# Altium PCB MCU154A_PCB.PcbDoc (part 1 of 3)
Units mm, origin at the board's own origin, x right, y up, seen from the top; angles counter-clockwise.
Board outline 105 x 85 mm, 2 copper layers (Top Layer, Bottom Layer), stack 1.6 mm thick; 186 components, 100 nets, 433 pads, 196 vias.
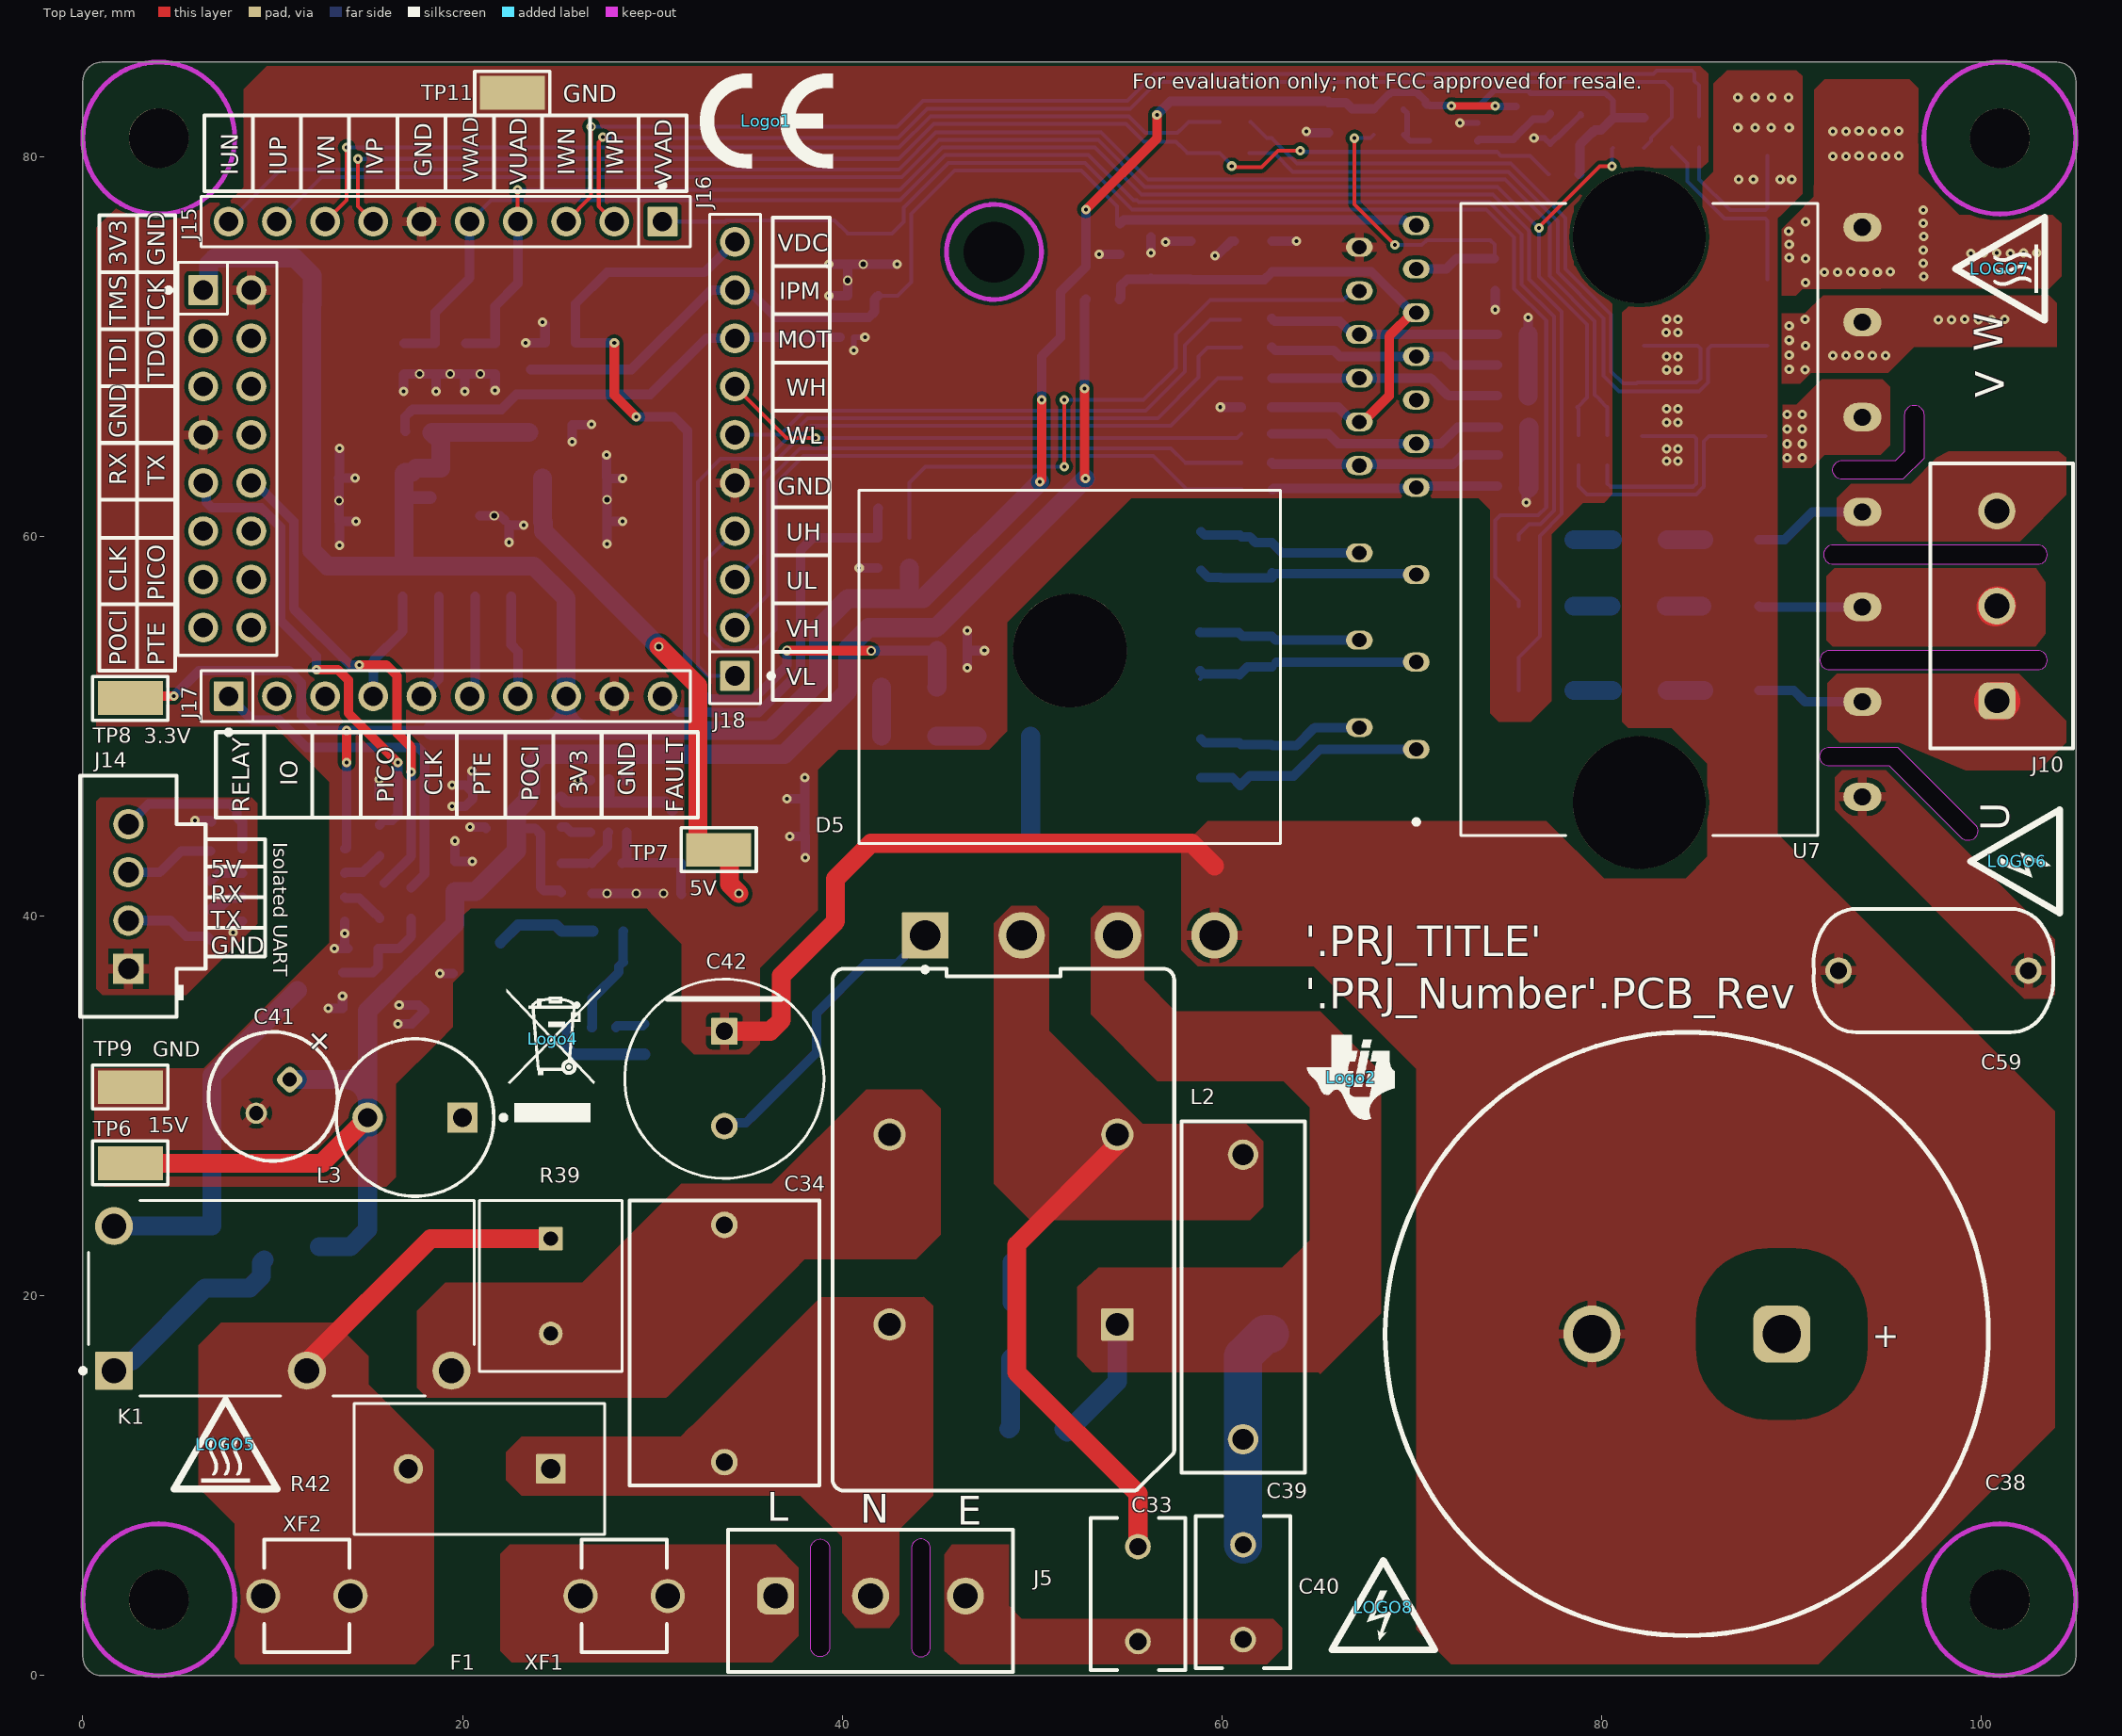
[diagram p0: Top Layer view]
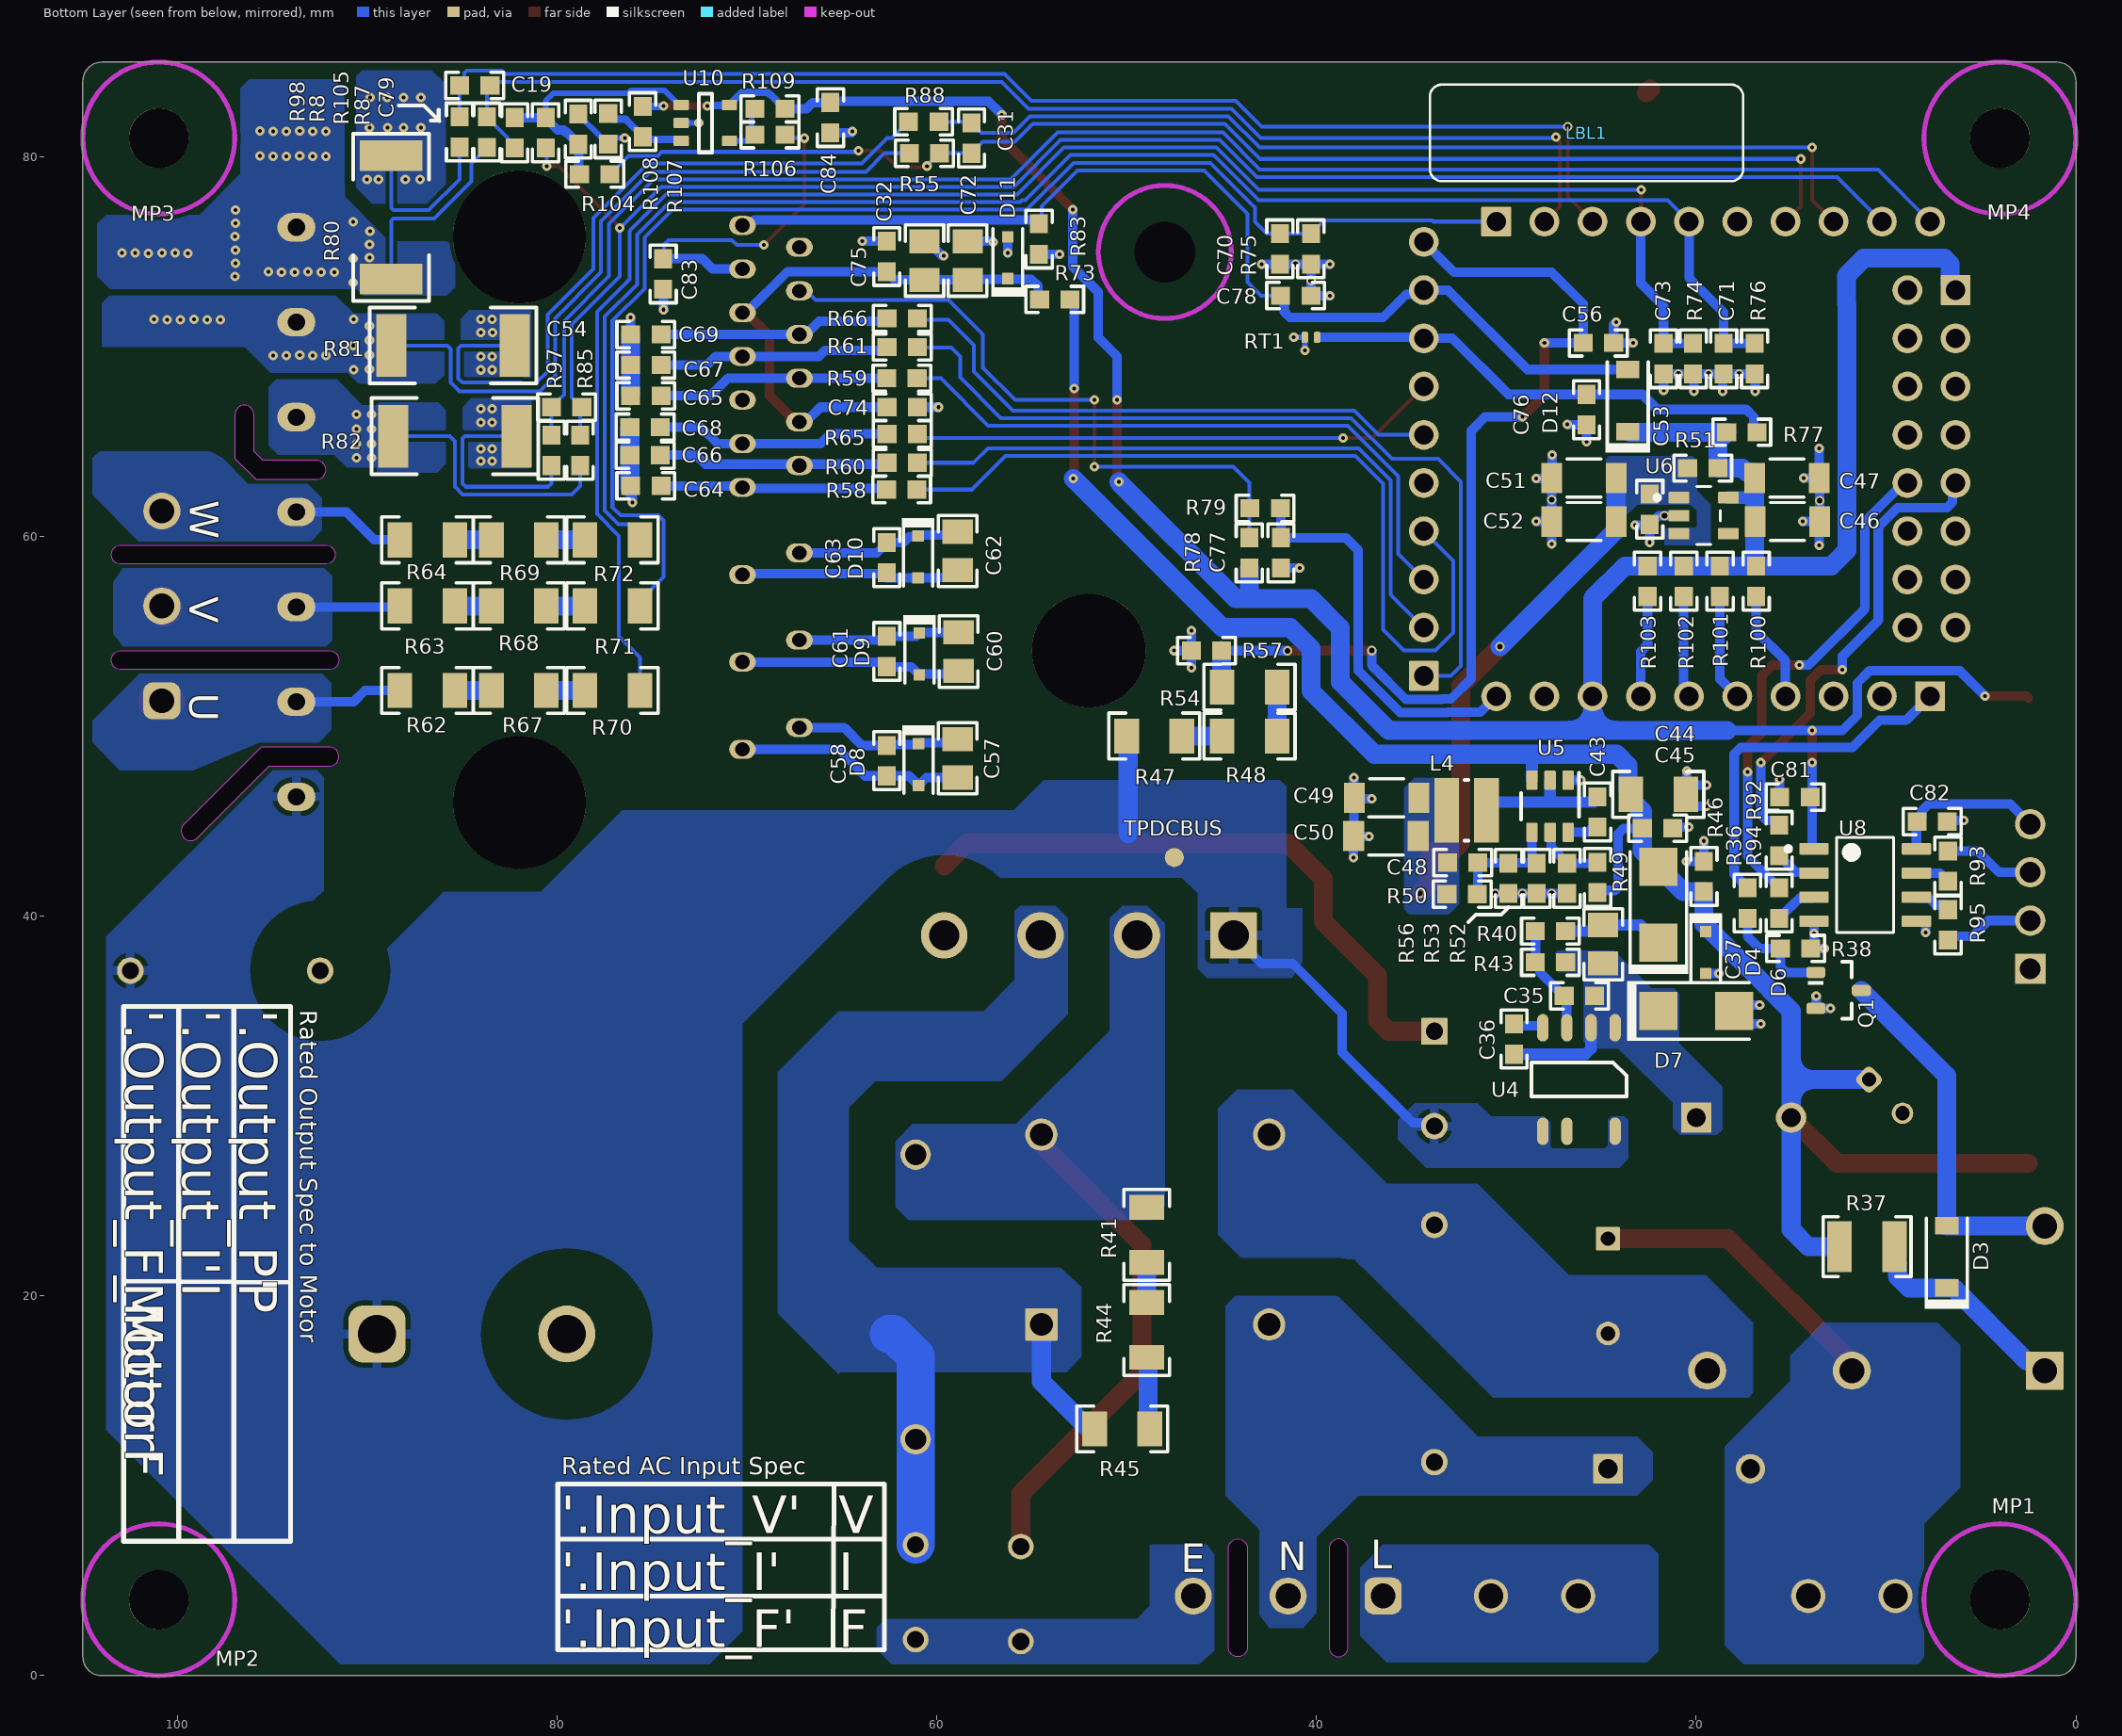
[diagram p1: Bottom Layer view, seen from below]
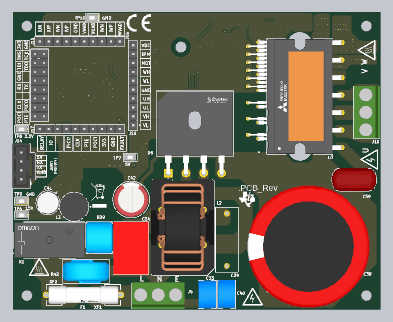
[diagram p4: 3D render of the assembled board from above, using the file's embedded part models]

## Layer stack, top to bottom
Top Solder: solder mask 0.0102, Solder Resist, Dk 3.5
Top Layer: signal copper 0.07
Dielectric1: core 1.46, FR-4 High Tg, Dk 4.8
Bottom Layer: signal copper 0.07
Bottom Solder: solder mask 0.0102, Solder Resist, Dk 3.5

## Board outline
1,0 cw(c1,1) 0,1 0,84 cw(c1,84) 1,85 104,85 cw(c104,84) 105,84 105,1 cw(c104,1) 104,0
cut-out: 92.695,63.017 cw(c92.695,63.517) 92.695,64.017 95.514,64.017 95.988,64.492 95.988,66.431 cw(c96.488,66.431) 96.988,66.431 96.988,64.115 95.89,63.017
cut-out: 92.209,58.554 103,58.554 ccw(c103,59.054) 103,59.554 92.209,59.554 ccw(c92.209,59.054)
cut-out: 92.017,52.995 103,52.995 ccw(c103,53.495) 103,53.995 92.017,53.995 ccw(c92.017,53.495)
cut-out: 92.017,47.918 cw(c92.017,48.418) 92.017,48.918 95.6,48.918 99.673,44.845 cw(c99.319,44.491) 98.966,44.138 95.185,47.918
cut-out: 43.652,1.5 ccw(c44.151,1.5) 44.651,1.5 44.651,6.7 ccw(c44.151,6.7) 43.651,6.7 43.652,6.7
cut-out: 38.348,1.5 38.348,6.7 cw(c38.848,6.7) 39.348,6.7 39.348,1.5 cw(c38.848,1.5)

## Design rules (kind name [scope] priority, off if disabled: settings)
AcuteAngle [All] p1: minimum=4.50000000000000E+0001 checktracksonly=FALSE
AssemblyTestPointUsage [All] p1: valid=2
BoardOutlineClearance BoardOutlineClearance_MountingHoles [OnCopper and InComponentClass('Mounting Holes')] p1: gap=0 ignorepadtopadclearanceinfootprint=FALSE
BoardOutlineClearance BoardOutlineClearance_Poly [OnCopper and IsPoly] p2: gap=0 ignorepadtopadclearanceinfootprint=FALSE
BoardOutlineClearance [OnCopper and Not InComponentClass('Logo') and not InComponentClass('FiducialMark') and not InRegion(1000,500,4000,800) and not InPoly] p3: gap=0 ignorepadtopadclearanceinfootprint=FALSE
Clearance PB+ToPB- [InNetClass('HV') vs InNetClass('LV_Signal')] p1: gap=3 ignorepadtopadclearanceinfootprint=TRUE
Clearance PB-ToACN [InNetClass('LV Signal') vs InNetClass('ACN')] p2: gap=3 ignorepadtopadclearanceinfootprint=TRUE
Clearance ACLToACN [InNetClass('ACL') vs InNetClass('ACN')] p3: gap=2 ignorepadtopadclearanceinfootprint=FALSE
Clearance ISOToAll [InNetClass('Isolation') vs not InNetClass('Isolation')   and (not  OnLayer('Keep-Out Layer'))] p4: gap=6 ignorepadtopadclearanceinfootprint=TRUE
Clearance PB-ToACL [InNetClass('LV Signal') vs InNetClass('ACL')] p5: gap=3 ignorepadtopadclearanceinfootprint=TRUE
Clearance PB+ToACL [InNetClass('V_BUS') vs InNetClass('ACL')] p6: gap=3 ignorepadtopadclearanceinfootprint=TRUE
Clearance PB+ToACN [InNetClass('V_BUS') vs InNetClass('ACN')] p7: gap=1.5 ignorepadtopadclearanceinfootprint=TRUE
Clearance SMTPadToTHHole [not IsVia and OnLayer('Multi-Layer') and not InComponent('J1') and not InComponent('J2') and not InComponent('J3') and not InComponent('J4') and not InComponent('J12') and PadIsPlated vs InSMTComponent and OnLayer('Bottom Layer') and not HasFootprint('TP_SM_1MM')] p8: gap=0.15 ignorepadtopadclearanceinfootprint=FALSE except(3: SMDPad-THPad)
Clearance [All vs not HasFootprint('fiducial10-20')] p9: gap=0.2 ignorepadtopadclearanceinfootprint=TRUE
ComponentClearance ComponentClearance_MountingHoles_FiducialMarks [InComponentClass('Mounting Holes') vs InComponentClass('FiducialMark')] p1: gap=1.27 collisioncheckmode=3 verticalgap=0.254 showdistances=FALSE
ComponentClearance ComponentClearance_Shunt [InComponentClass('Header') vs InComponentClass('Shunt')] p2: gap=0 collisioncheckmode=3 verticalgap=0 showdistances=FALSE
ComponentClearance ComponentClearance_Logo [InComponentClass('Logo')] p3: gap=0.762 collisioncheckmode=3 verticalgap=0.254 showdistances=FALSE
ComponentClearance ComponentClearance_ScrewToNut [(HasFootprint('NY PMS 440 0025 PH')) vs (HasFootprint('Keystone_1902C'))] p4: gap=0.127 collisioncheckmode=3 verticalgap=0.254 showdistances=FALSE
ComponentClearance ComponentClearance_MountingHoles [InComponentClass('Mounting Holes')] p5: gap=2.54 collisioncheckmode=3 verticalgap=2540 showdistances=FALSE
ComponentClearance ComponentClearance_SmallPassives [HasFootprint('0201*') or HasFootprint('0402*') or HasFootprint('0508') or HasFootprint('0603*') or HasFootprint('0612') or HasFootprint('0805*') or HasFootprint('0815*') or HasFootprint('0830*') or HasFootprint('1206*') or HasFootprint('1210*') or HasFootprint('1808*') or HasFootprint('1812*') or HasFootprint('1825*') or HasFootprint('2010*') or HasFootprint('2220*') or HasFootprint('2225*') or HasFootprint('2512*') or HasFootprint('2728*') or HasFootprint('3518*') vs HasFootprint('0201*') or HasFootprint('0402*') or HasFootprint('0508') or HasFootprint('0603*') or HasFootprint('0612') or HasFootprint('0805*') or HasFootprint('0815*') or HasFootprint('0830*') or HasFootprint('1206*') or HasFootprint('1210*') or HasFootprint('1808*') or HasFootprint('1812*') or HasFootprint('1825*') or HasFootprint('2010*') or HasFootprint('2220*') or HasFootprint('2225*') or HasFootprint('2512*') or HasFootprint('2728*') or HasFootprint('3518*')] p6: gap=0.38 collisioncheckmode=3 verticalgap=0.254 showdistances=FALSE
ComponentClearance ComponentClearance_THtoSMT [IsThruComponent vs IsSMTComponent] p7: gap=0.762 collisioncheckmode=3 verticalgap=0.762 showdistances=FALSE
ComponentClearance ComponentClearance_THtoTH [IsThruComponent vs IsThruComponent] p8: gap=0.508 collisioncheckmode=3 verticalgap=0.762 showdistances=FALSE
ComponentClearance [All] p9: gap=0.508 collisioncheckmode=3 verticalgap=0.254 showdistances=FALSE
DiffPairsRouting [All] p1: maxlimit=2.54 minlimit=0.254 mostfreqgap=0.254 toplayer_minwidth=0.381 toplayer_maxwidth=0.381 toplayer_prefwidth=0.381 bottomlayer_minwidth=0.381 bottomlayer_maxwidth=0.381 bottomlayer_prefwidth=0.381 maxuncoupledlength=25.4
FabricationTestPointUsage TestPointUsage [All] p1: valid=2 allowmultiple=FALSE
FabricationTestpoint Testpoint [All] p1: side=3 testpointundercomponent=TRUE minsize=1.016 maxsize=2.54 preferedsize=1.524 minholesize=0 maxholesize=1.016 preferedholesize=0.813 testpointgrid=0.025 allowsidetop=TRUE allowsidebottom=TRUE usegrid=TRUE gridtolerance=0
FanoutControl Fanout_LCC [IsLCC] p1: bgadir=Out bgaviamode=Centered fanoutstyle=Auto fanoutdirection=Alternating viagrid=0.025 // Fanout_LCC (Default Rule)
FanoutControl Fanout_BGA [IsBGA] p2: bgadir=Out bgaviamode=Centered fanoutstyle=Auto fanoutdirection=Alternating viagrid=0.025 // Fanout_BGA (Default Rule)
FanoutControl Fanout_Default [All] p4: bgadir=Out bgaviamode=Centered fanoutstyle=Auto fanoutdirection=Alternating viagrid=0.025 // Fanout_Default (Default Rule)
FanoutControl Fanout_Small [(CompPinCount < 5)] p5: bgadir=Out bgaviamode=Centered fanoutstyle=Auto fanoutdirection=OutThenIn viagrid=0.025 // Fanout_Small (Default Rule)
HoleSize [All] p1: absolutevalues=TRUE maxlimit=6.375 minlimit=0.2 maxpercent=80.000 minpercent=20.000
MinimumAnnularRing MinimumAnnularRing_ThermalPadVias [IsVia and InAnyComponent] p1: minimumring=0.15
MinimumAnnularRing [All] p2: minimumring=0.2
MinimumSolderMaskSliver MinimumSolderMaskSliver_Logo [InComponentClass('Logo') vs InComponentClass('Logo')] p1: minsoldermaskwidth=0.018
MinimumSolderMaskSliver [All] p2: minsoldermaskwidth=0.1
PlaneConnect [All] p1: planeconnectstyle=Direct reliefexpansion=0.254 reliefentries=4 reliefconductorwidth=0.254 reliefairgap=0.254
PolygonConnect "Thermal relief" [All vs InNet('GND') or innet('GND_ISO')  or innet('ubus')] p1: thpad.connectstyle=Relief thpad.reliefconductorwidth=0.5 thpad.reliefentries=4 thpad.polygonreliefangle="90 Angle" thpad.airgapwidth=0.254 smdpad.connectstyle=Direct smdpad.reliefconductorwidth=0.5 smdpad.reliefentries=4 smdpad.polygonreliefangle="90 Angle" smdpad.airgapwidth=0.254 via.connectstyle=Direct via.reliefconductorwidth=0.5 via.reliefentries=4 via.polygonreliefangle="90 Angle" via.airgapwidth=0.254
PolygonConnect [All] p2: connectstyle=Direct reliefconductorwidth=0.254 reliefentries=4 polygonreliefangle="90 Angle" airgapwidth=0.254
RoutingVias ThermalPadVias [IsVia and InAnyComponent] p1: holewidth=0.2 width=0.5 viastyle="Through Hole" minholewidth=0.2 minwidth=0.5 maxholewidth=0.33 maxwidth=0.6
RoutingVias [All] p2: holewidth=0.2 width=0.5 viastyle="Through Hole" minholewidth=0.2 minwidth=0.4 maxholewidth=1 maxwidth=1.4
SilkToBoardRegionClearance [Not ((IsComment or IsDesignator) And (Hide <> 'False')) and not InRegion(1000,500,4000,800)] p1:
SilkToSilkClearance SilkToSilkClearance_Pb-FreeLogo [(HasFootprint('Pb-Free_Overlay_Medium') OR HasFootprint('Pb-Free_Overlay_Small')) vs (HasFootprint('Pb-Free_Overlay_Medium') OR HasFootprint('Pb-Free_Overlay_Small'))] p1: silktosilkclearance=0
SilkToSilkClearance [All] p2: silktosilkclearance=0.1
SilkToSolderMaskClearance SilkToComponentPadClearance [(IsPad or IsFill or IsRegion) and InAnycomponent] p1: minsilkscreentomaskgap=0.127 clearancetoexposedcopper=TRUE
SilkToSolderMaskClearance "Silk to Solder Mask Opening" [All] p2: minsilkscreentomaskgap=0.1 clearancetoexposedcopper=FALSE
SolderMaskExpansion [All] p1: expansion=0.05 istentingtop=FALSE
UnRoutedNet [All] p1: checkbadconnections=TRUE
Width [All] p1: maxlimit=5 minlimit=0.2 preferedwidth=0.3 minimp=50.000000 maximp=50.000000 favimp=50.000000 checkconnectedcopper=TRUE
14 further rules are at their usual default settings.

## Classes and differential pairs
component class MCU154A_Main: J5 J10
net class LV_Signal: 3.3V 5V 5V_ISO 15V GND GND_ISO IPM_15V IPM_CIN IPM_FAULT IPM_PWM_UH IPM_PWM_UL IPM_PWM_VH IPM_PWM_VL IPM_PWM_WH IPM_PWM_WL IPM_TEMP_AD IU_N IU_P IV_N IV_P IW_N IW_P MCU_TCK MCU_TDI MCU_TDO MCU_TMS MISC_IO MOTOR_TEMP_AD NetC43_1 NetC43_2 NetC48_2 NetC79_1 NetD3_1 NetD3_2 NetQ1_1 NetR8_1 NetR49_1 NetR55_1 NetR78_2 NetR82_2 NetR92_2 NetR93_1 NetR94_2 NetR95_1 NetR106_1 NetR107_1 NetU4_6 NetU6_4 NetU7_12 PWM_UH PWM_UL PWM_VH PWM_VL PWM_WH PWM_WL RELAY SPI_CLK(AI) SPI_CLK(DAC) SPI_PICO(AI) SPI_PICO(DAC) SPI_POCI(AI) SPI_POCI(DAC) SPI_PTE(AI) SPI_PTE(DAC) UART_RX UART_RX_ISO UART_TX UART_TX_ISO VDC_AD VU_AD VV_AD VW_AD
net class HV: Ubus
net class ACN: NetC39_2 NetR44_1 NEU
net class ACL: NetC33_1 NetC34_1 NetK1_2
component class Designator: C81 C82 J15 J16 J17 J18 R92 R93 R94 R95 R100 R101 R102 R103 U8
component class Logo: Logo2
component class Label: LBL1
component class Designator: C19 C31 C32 C54 C57 C58 C59 C60 C61 C62 C63 C64 C65 C66 C67 C68 C69 C70 C71 C72 C73 C74 C75 C76 C77 C78 C79 C83 C84 D8 D9 D10 D11 D12 R8 R55 R58 R59 R60 R61 R62 R63 R64 R65 R66 R67 R68 R69 R70 R71 R72 R73 R74 R75 R76 R77 R78 R79 R80 R81 R82 R83 R85 R87 R88 R97 R98 R104 R105 R106 R107 R108 R109 RT1 U7 U10

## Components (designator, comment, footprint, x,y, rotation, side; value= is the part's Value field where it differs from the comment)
C19 "GRM188R71E102KA01D" 0603 84.352,83.773 r180 bottom value=1000pF
C31 "GRM188R71E102KA01D" 0603 58.183,81 r270 bottom value=1000pF
C32 "GRM21BR6YA106KE43L" 0805_HV 60.662,74.548 r90 bottom value=10uF
C33 "DE2E3KY222MA2BM01F" KY_800x500x1100 55.588,4.3 r270 top value=2200pF
C34 "890324024005" WCAP-FTX2_1500x1000x1600 33.8,17.5 r270 top value=0.47uF
C35 "GRM1885C1H200JA01D" 0603 26.156,35.81 r180 bottom value=20pF
C36 "GCM188R71H104KA57D" 0603 29.6,33.537 r270 bottom value=0.1uF
C37 "GRM219R71H334KA88D" 0805_HV 24.907,38.531 r270 bottom value=0.33uF
C38 "861141486026" WCAP-AI3H_3500x5700 84.5,18 r180 top value=680uF
C39 "890324025017" WCAP-FTX2_1800x600x1200 61.126,19.95 r270 top value=0.1uF
C40 "DE2E3KY222MA2BM01F" KY_800x500x1100 61.126,4.4 r90 top value=2200pF
C41 "35ZLJ100M6.3X11" Rubycon_630x1100 10.016,30.516 r225 top value=100uF
C42 "860241375002" FP-860241375002_RADIAL-MFG 33.8,31.45 r270 top locked value=10µF
C43 "GCM188R71H104KA57D" 0603 25.2,45.5 r90 bottom value=0.1uF
C44 "GRM319R6YA106KA12D" 1206 22,46.426 r180 bottom value=10uF
C45 "GCM188R71H104KA57D" 0603 22.038,44.641 r180 bottom value=0.1uF
C46 "GRM31CR71E106KA12L" 1206_180 15.2,60.8 r180 bottom value=10uF
C47 "GRM31CR71E106KA12L" 1206_180 15.224,63.089 r180 bottom value=10uF
C48 "GRM1885C1H101JA01D" 0603 32.307,42.831 r180 bottom value=100pF
C49 "GRM31CR71E106KA12L" 1206_180 36.349,44.23 r0 bottom value=10uF
C50 "GRM31CR71E106KA12L" 1206_180 36.309,46.25 r0 bottom value=10uF
C51 "GRM31CR71E106KA12L" 1206_180 25.921,63.089 r0 bottom value=10uF
C52 "GRM31CR71E106KA12L" 1206_180 25.921,60.8 r0 bottom value=10uF
C53 "GCM188R71H104KA57D" 0603 22.452,61.445 r270 bottom value=0.1uF
C54 "GRM188R71E102KA01D" 0603 79.515,66.825 r180 bottom value=1000pF
C56 "GRM188R71H473KA61D" 0603 25.152,70.209 r180 bottom value=0.047uF
C57 "GRM21BR6YA106KE43L" 0805_HV 58.913,48.326 r90 bottom value=10uF
C58 "GCM188R71H104KA57D" 0603 62.644,48.2 r90 bottom value=0.1uF
C59 "ECW-FD2W474Q1" ECWFD_1260x650x1270 97.5,37.142 r180 top value=0.47uF
C60 "GRM21BR6YA106KE43L" 0805_HV 58.864,53.952 r90 bottom value=10uF
C61 "GCM188R71H104KA57D" 0603 62.644,53.952 r90 bottom value=0.1uF
C62 "GRM21BR6YA106KE43L" 0805_HV 58.913,59.249 r90 bottom value=10uF
C63 "GCM188R71H104KA57D" 0603 62.646,58.9 r90 bottom value=0.1uF
C64 "GRM188R71H221KA01D" 0603 75.34,62.679 r180 bottom value=220pF
C65 "GRM188R71H221KA01D" 0603 75.34,67.424 r180 bottom value=220pF
C66 "GRM188R71H221KA01D" 0603 75.378,64.297 r180 bottom value=220pF
C67 "GRM188R71H221KA01D" 0603 75.34,69.04 r180 bottom value=220pF
C68 "GRM188R71H221KA01D" 0603 75.378,65.772 r180 bottom value=220pF
C69 "GRM188R71H221KA01D" 0603 75.34,70.65 r180 bottom value=220pF
C70 "GRM188R71H473KA61D" 0603 41.933,75.163 r270 bottom value=0.047uF
C71 "GRM188R71H473KA61D" 0603 18.559,69.378 r270 bottom value=0.047uF
C72 "GRM21BR6YA106KE43L" 0805_HV 58.386,74.548 r90 bottom value=10uF
C73 "GRM188R71H473KA61D" 0603 21.721,69.378 r270 bottom value=0.047uF
C74 "GCM188R71H104KA57D" 0603 61.835,66.825 r180 bottom value=0.1uF
C75 "GCM188R71H104KA57D" 0603 62.646,74.764 r90 bottom value=0.1uF
C76 "GCM188R71H104KA57D" 0603 25.781,66.695 r270 bottom value=0.1uF
C77 "GRM188R71E102KA01D" 0603 41.883,59.15 r270 bottom value=1000pF
C78 "GRM188R71E102KA01D" 0603 41.1,72.7 r0 bottom value=1000pF
C79 "GRM1885C1H101JA01D" 0603 78.897,81.466 r90 bottom value=100pF
C81 "GRJ188R71E105KE11D" 0603 14.8,46.285 r180 bottom value=1uF
C82 "GRJ188R71E105KE11D" 0603 7.567,44.994 r180 bottom value=1uF
C83 "GRM188R71E102KA01D" 0603 74.43,73.844 r270 bottom value=1000pF
C84 "GCM188R71H104KA57D" 0603 65.619,82.08 r270 bottom value=0.1uF
D3 "BAT54T1G" SOD-123 6.8,22.063 r90 bottom value=30V
D4 "US1M-13-F" SMA 22,40.614 r90 bottom value=1000V
D5 "GBU15J" FP-GBU8J_Horizontal_Face_Down_SIP4-MFG 52,53.15 r0 top locked
D6 "MMSZ5248BS-7-F" SOD-323 19.5,38.1 r270 bottom value=18V
D7 "US1M-13-F" SMA 20,35.016 r180 bottom value=1000V
D8 "MMSZ5248BS-7-F" SOD-323 60.974,48 r270 bottom value=18V
D9 "MMSZ5248BS-7-F" SOD-323 60.926,53.823 r270 bottom value=18V
D10 "MMSZ5248BS-7-F" SOD-323 60.999,58.935 r270 bottom value=18V
D11 "MMSZ5248BS-7-F" SOD-323 56.274,74.699 r90 bottom value=18V
D12 "BAT54T1G" SOD-123 23.61,67.171 r90 bottom value=30V
F1 "0215008.HXP" FP-0215008.HXP_FUSE_CARTRIDGE-MFG 20.146,4.2 r0 top
J5 "691137710003" 691137710003 41.5,3.95 r0 top
J10 "691137710003" 691137710003 101.09,56.351 r90 top
J14 "70543-0038" Molex_70543-0038 2.4,41.05 r90 top
J15 "TSW-108-07-T-D" FP-TSW-108-07-T-D_HDR16-MFG 7.61,64.1 r270 top
J16 "TSW-110-07-T-S" FP-TSW-110-07-T-S_HDR10-MFG 19.11,76.6 r180 top
J17 "TSW-110-07-T-S" FP-TSW-110-07-T-S_HDR10-MFG 19.11,51.6 r0 top
J18 "TSW-110-07-T-S" FP-TSW-110-07-T-S_HDR10-MFG 34.36,64.1 r90 top
K1 "G5Q-1A4-EU DC12" "FP-G5Q-1A4-EU DC12_PTH_RELAY_20MM0_10MM0-MFG" 10.46,19.875 r0 top
L2 "7448040707" WE-CMBNC_L 48.5,23.5 r180 top locked value=7mH
L3 "768772182" WE-TI_8095 17.5,29.4 r180 top value=1.8mH
L4 "78438335068" WE-MAIA_3015 32.1,45.595 r0 bottom value=6.8uH
LBL1 "THT-14-423-10" Label_650x200 25.781,81.276 r180 bottom
Logo1 "CE Mark" CE_Mark_5mm 36,81.9 r0 top
Logo2 "Texas Instruments" TI_Symbol_Overlay_Small 66.8,31.518 r0 top
Logo3 "FCC disclaimer" FCC_disclaimer 47.377,95 r0 top
Logo4 "WEEE logo" WEEE_Minimum 24.74,33.543 r0 top
LOGO5 "CAUTION HOT SURFACE" IEC_HotSurface_Small 7.518,12.2 r0 top
LOGO6 "DANGER HIGH VOLTAGE" IEC_HighVoltage_Small 101.91,42.9 r90 top
LOGO7 "CAUTION HOT SURFACE" IEC_HotSurface_Small 101,74.115 r90 top
LOGO8 "DANGER HIGH VOLTAGE" IEC_HighVoltage_Small 68.511,3.6 r0 top
M46 "Comment" MARK 559.6,31.8 r0 top
M47 "Comment" Toolinghole 544.6,30.3 r0 top
M49 "Comment" MARK 554.6,31.8 r0 top
M50 "Comment" MARK 399.6,31.8 r0 top
M51 "Comment" MARK 399.602,138.799 r0 top
M52 "Comment" MARK 559.6,138.8 r0 top
M53 "Comment" Toolinghole 409.6,30.3 r0 top
M54 "Comment" Toolinghole 409.602,140.299 r0 top
M55 "Comment" Toolinghole 549.6,140.3 r0 top
M56 "Comment" Arrow 424.6,140.3 r0 top
M57 "Comment" Arrow 467.6,140.3 r180 bottom
M57 "Comment" "Bad Mark" 484.6,31.8 r0 top
M58 "Comment" "Bad Mark" 474.6,31.8 r0 top
M58 "Comment" "White oil-26X4" 524.6,28.3 r0 top
MP1 "970130365" FP-970130365_SPCAER_M3-MFG 4,4 r180 bottom locked
MP2 "970130365" FP-970130365_SPCAER_M3-MFG 101,4 r180 bottom locked
MP3 "970130365" FP-970130365_SPCAER_M3-MFG 101,81 r180 bottom
MP4 "970130365" FP-970130365_SPCAER_M3-MFG 4,81 r180 bottom
Q1 "2N7002P,215" SOT-23 12.5,36.1 r180 bottom value=60V
R8 "RC0603FR-0720RL" 0603 83.715,81.315 r90 bottom value=20.0
R36 "RC0603FR-071KL" 0603 17.3,40.7 r270 bottom value=1.00k
R37 "RC1210FR-07180RL" 1210 11,22.6 r180 bottom value=180
R38 "RC0603FR-0710KL" 0603 14.768,38.309 r0 bottom value=10.0k
R39 "B59770C0120A070" FP-B59770C0120A070_RADIAL-MFG 24.65,20.525 r270 top value=70¦¸
R40 "RC0603FR-07133KL" 0603 27.68,39.222 r180 bottom value=133k
R41 "RC1206FR-07100KL" 1206 48.952,23.223 r90 bottom value=100k
R42 "IsoM3-275-B-L2" FP-IsoM3-275-B-L2_RADIAL-MFG 20.9,10.9 r180 top
R43 "RC0603FR-0710KL" 0603 27.68,37.583 r0 bottom value=10.0k
R44 "RC1206FR-07100KL" 1206 48.952,18.213 r90 bottom value=100k
R45 "RC1206FR-07100KL" 1206 50.239,13 r180 bottom value=100k
R46 "RC0603FR-0720KL" 0603 19.6,42.1 r270 bottom value=20.0k
R47 "RC1206FR-07332KL" 1206 48.555,49.5 r0 bottom value=332k
R48 "RC1206FR-07332KL" 1206 43.535,49.5 r0 bottom value=332k
R49 "RC0603FR-071M5L" 0603 25.2,42.052 r270 bottom value=1.50Meg
R50 "RC0603FR-07100KL" 0603 32.337,41.169 r0 bottom value=100k
R51 "RC0603JR-070RL" 0603 19.659,63.612 r180 bottom value=0
R52 "RC0603FR-07133KL" 0603 26.811,42 r90 bottom value=133k
R53 "RC0603FR-0713K7L" 0603 28.401,42 r90 bottom value=13.7k
R54 "RC1206FR-07332KL" 1206 43.535,52.073 r180 bottom value=332k
R55 "RC0603FR-0720RL" 0603 60.662,80.2 r180 bottom value=20.0
R56 "RC0603FR-0720KL" 0603 29.891,42 r90 bottom value=20.0k
R57 "RC0603FR-078K2L" 0603 45.8,54 r180 bottom value=8.20k
R58 "RC0603FR-07100RL" 0603 61.862,62.484 r0 bottom value=100
R59 "RC0603FR-07100RL" 0603 61.844,68.349 r0 bottom value=100
R60 "RC0603FR-07100RL" 0603 61.835,63.898 r0 bottom value=100
R61 "RC0603FR-07100RL" 0603 61.835,69.992 r0 bottom value=100
R62 "RC1206FR-07332KL" 1206 86.847,51.9 r0 bottom value=332k
R63 "RC1206FR-07332KL" 1206 86.847,56.351 r0 bottom value=332k
R64 "RC1206FR-07332KL" 1206 86.847,59.835 r0 bottom value=332k
R65 "RC0603FR-07100RL" 0603 61.835,65.414 r0 bottom value=100
R66 "RC0603FR-07100RL" 0603 61.835,71.502 r0 bottom value=100
R67 "RC1206FR-07332KL" 1206 82.029,51.9 r0 bottom value=332k
R68 "RC1206FR-07332KL" 1206 82.029,56.351 r0 bottom value=332k
R69 "RC1206FR-07332KL" 1206 82.029,59.835 r0 bottom value=332k
R70 "RC1206FR-07332KL" 1206 77.1,51.9 r0 bottom value=332k
R71 "RC1206FR-07332KL" 1206 77.1,56.351 r0 bottom value=332k
R72 "RC1206FR-07332KL" 1206 77.1,59.835 r0 bottom value=332k
R73 "RC0603JR-070RL" 0603 53.8,72.5 r0 bottom value=0
R74 "RC0603FR-078K2L" 0603 20.166,69.378 r90 bottom value=8.20k
R75 "RC0603FR-078K2L" 0603 40.3,75.163 r90 bottom value=8.20k
R76 "RC0603FR-078K2L" 0603 16.923,69.378 r90 bottom value=8.20k
R77 "RC0603FR-071KL" 0603 17.6,65.5 r0 bottom value=1.00k
R78 "RC0603FR-0710KL" 0603 43.545,59.15 r90 bottom value=10.0k
R79 "RC0603FR-07100RL" 0603 42.714,61.496 r0 bottom value=100
R80 "CSRN2512FT50L0" CSRN2512 88.754,76.823 r270 bottom value=0.05
R81 "CSRN2512FT50L0" CSRN2512 85.5,70.068 r0 bottom value=0.05
R82 "CSRN2512FT50L0" CSRN2512 85.397,65.297 r0 bottom value=0.05
R83 "RC0603FR-075K1L" 0603 54.625,75.682 r90 bottom value=5.10k
R85 "RC0603FR-0720RL" 0603 78.807,64.55 r90 bottom value=20.0
R87 "RC0603FR-075K1L" 0603 80.618,81.28 r90 bottom value=5.10k
R88 "RC0603FR-0720RL" 0603 60.702,81.859 r180 bottom value=20.0
R92 "RC0603FR-07100RL" 0603 15.633,44 r270 bottom value=100
R93 "RC0603FR-071KL" 0603 6.734,42.65 r90 bottom value=1.00k
R94 "RC0603FR-071KL" 0603 15.633,40.7 r270 bottom value=1.00k
R95 "RC0603FR-07100RL" 0603 6.738,39.55 r270 bottom value=100
R97 "RC0603FR-0720RL" 0603 80.315,64.55 r90 bottom value=20.0
R98 "RC0603FR-0720RL" 0603 85.152,81.318 r90 bottom value=20.0
R100 "RC0603FR-0710KL" 0603 16.844,57.654 r270 bottom value=10.0k
R101 "RC0603FR-0710KL" 0603 18.751,57.654 r270 bottom value=10.0k
R102 "RC0603FR-0710KL" 0603 20.659,57.654 r270 bottom value=10.0k
R103 "RC0603FR-0710KL" 0603 22.566,57.654 r270 bottom value=10.0k
R104 "RC0603FR-075K1L" 0603 78.033,79.098 r0 bottom value=5.10k
R105 "RC0603FR-075K1L" 0603 82.25,81.28 r90 bottom value=5.10k
R106 "RC0603FR-07100RL" 0603 68.8,81.173 r180 bottom value=100
R107 "RC0603FR-0720KL" 0603 75.505,81.864 r90 bottom value=20.0k
R108 "RC0603FR-071KL" 0603 77.32,81.487 r90 bottom value=1.00k
R109 "RC0603FR-0720KL" 0603 68.8,82.542 r0 bottom value=20.0k
RT1 "TMP6131DECR" DEC0002A 40.3,70.5 r180 bottom
TP6 "5015" Testpoint_Keystone_Miniature 2.5,27 r180 top
TP7 "5015" Testpoint_Keystone_Miniature 33.5,43.5 r180 top
TP8 "5015" Testpoint_Keystone_Miniature 2.5,51.5 r0 top
TP9 "5015" Testpoint_Keystone_Miniature 2.5,31 r180 top
TP11 "5015" Testpoint_Keystone_Miniature 22.626,83.382 r0 top
TPDCBUS "TP_SM_1MM" TP_SM_1MM 47.5,43.1 r0 bottom
U4 "UCC28881DR" D0007A_N 26.18,31.406 r270 bottom
U5 "TPS54202DDCR" DDC0006A_N 27.7,45.8 r270 bottom
U6 "TLV74033PDBVR" DBV0005A-MFG 19.609,61.11 r180 bottom
U7 "SLIMDIP-M" FP-SLIMDIP-S_SLIMDIP-MFG 82,60.9 r90 top locked
U8 "ISO6721BQDRQ1" D0008A-MFG 11.1,41.65 r180 bottom
U10 "LMV331QDBVRQ1" DBV0005A_L 72.204,81.798 r180 bottom
XF1 "01000056Z" Littelfuse_0100-0020_54_56 28.515,4.2 r0 top value=10A
XF2 "01000056Z" Littelfuse_0100-0020_54_56 11.8,4.2 r0 top value=10A

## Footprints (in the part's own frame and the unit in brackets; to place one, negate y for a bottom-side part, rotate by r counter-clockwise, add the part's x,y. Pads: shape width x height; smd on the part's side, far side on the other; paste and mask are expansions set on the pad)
0603 [mm] "0603 from SM-752 data"
  rect 1x0.95 smd: 1(-0.8,0) 2(0.8,0)
  silkscreen extent -1.52,-0.69 1.52,0.69, body extent -0.87,-0.47 0.87,0.47, height 1
0805_HV [mil] "0805 with 30mil clearance between pads"
  rect 50x63 smd: 1(-40,0) 2(40,0)
  silkscreen extent -74,-40 74,40, body extent -43,-29 43,29, height 57
1206 [mm] "1206 from SM-752 data"
  rect 1.3x1.85 smd: 1(-1.45,0) 2(1.45,0)
  silkscreen extent -2.4,-1.21 2.4,1.21, body extent -1.7,-0.9 1.7,0.9, height 1.35
1206_180 [mm] "1206_180"
  rect 1.1x1.6 smd: 1(-1.7,0) 2(1.7,0)
  silkscreen extent -0.9,-1 0.9,1, body extent -1.75,-0.95 1.75,0.95, height 1.8
1210 [mm] "1210 from SM-752 data"
  rect 1.3x2.7 smd: 1(-1.45,0) 2(1.45,0)
  silkscreen extent -2.32,-1.57 2.32,1.57, body extent -1.7,-1.35 1.7,1.35, height 1.35
691137710003 [mm] "Horizontal Cable Entry with Pressure Clamp, pitch 5mm, 03p"
  rrect50% 1.95x1.95 hole 1.3: 1(-5,0.25)
  round 1.95 hole 1.3: 2(0,0.25) 3(5,0.25)
  silkscreen extent -7.5,-3.75 7.5,3.75, body extent -7.5,-3.75 7.5,3.75, height 11.6
Arrow [mm] "·½Ïò¼ýÍ·"
  silkscreen extent 0,-2 43,2
"Bad Mark" [mm]
  round 2 on Bottom Solder: 2(0,0)
  round 2 on Top Solder: 2(0,0)
  Top Layer pour cut-out: -1.051,0 -0.971,-0.402 -0.743,-0.743 -0.402,-0.971 0,-1.051 0,-1.051 0.402,-0.971 0.743,-0.743 0.971,-0.402 1.051,0 1.051,0 0.971,0.402 0.743,0.743 0.402,0.971 0,1.051 0,1.051 -0.402,0.971 -0.743,0.743 -0.971,0.402 -1.051,0
  Top Layer region: -0.5,-0.25 -0.5,0.25 0.5,0.25 0.5,-0.25
  Top Layer region: -0.25,0.5 0.25,0.5 0.25,-0.5 -0.25,-0.5
  Bottom Layer pour cut-out: 1.051,0 0.971,-0.402 0.743,-0.743 0.402,-0.971 0,-1.051 0,-1.051 -0.402,-0.971 -0.743,-0.743 -0.971,-0.402 -1.051,0 -1.051,0 -0.971,0.402 -0.743,0.743 -0.402,0.971 0,1.051 0,1.051 0.402,0.971 0.743,0.743 0.971,0.402 1.051,0
  Bottom Layer region: 0.25,0.5 -0.25,0.5 -0.25,-0.5 0.25,-0.5
  Bottom Layer region: 0.5,-0.25 0.5,0.25 -0.5,0.25 -0.5,-0.25
CE_Mark_5mm [mm] "Minimum text height for CE Mark"
  silkscreen extent -3.5,-2.5 3.5,2.5
CSRN2512 [mm] "STACKPOLE"
  rect 1.6x3.3 smd: 1(-3.25,0) 2(3.25,0)
  silkscreen extent -4.4,-2 4.4,2, body extent -3.27,-1.65 3.27,1.65, height 0.7
D0007A_N [mm] "SOIC, 7-Leads, Body 4.9x3.9mm, Pitch 1.27mm, IPC Medium Density"
  oval 1.45x0.6 smd: 1(-2.725,1.905) 2(-2.725,0.635) 3(-2.725,-0.635) 4(-2.725,-1.905) 5(2.725,-1.905) 6(2.725,-0.635) 8(2.725,1.905)
  silkscreen extent -0.9,-2.5 0.9,2.5, body extent -3.01,-2.45 3.01,2.45, height 1.75
D0008A-MFG [mm]
  rrect17% 1.55x0.6 smd paste+0: 1(-2.7,1.905) 2(-2.7,0.635) 3(-2.7,-0.635) 4(-2.7,-1.905) 5(2.7,-1.905) 6(2.7,-0.635) 7(2.7,0.635) 8(2.7,1.905)
  silkscreen extent -4.17,-2.5 1.5,2.5, body extent -3,-2.45 3,2.45, height 1.75
DBV0005A-MFG [mm]
  rrect17% 1.1x0.6 smd paste+0 mask+0: 1(-1.3,0.95) 2(-1.3,0) 3(-1.3,-0.95) 4(1.3,-0.95) 5(1.3,0.95)
  silkscreen extent -2.58,-1.53 0.87,1.53, body extent -1.4,-1.45 1.4,1.45, height 1.45
DBV0005A_L [mm] "SOT23, 5-Leads, Body 2.9x1.6mm, Pitch 0.95mm, Lead Span 2.8mm, IPC High Density"
  rrect18% 0.8x0.55 smd: 1(-1.275,0.95) 2(-1.275,0) 3(-1.275,-0.95) 4(1.275,-0.95) 5(1.275,0.95)
  silkscreen extent -0.35,-1.55 0.35,1.55, body extent -1.42,-1.46 1.42,1.46, height 1.09
DDC0006A_N [mm]
  rrect17% 1x0.6 smd: 1(-1.375,0.95) 2(-1.375,0) 3(-1.375,-0.95) 4(1.375,-0.95) 5(1.375,0) 6(1.375,0.95)
  silkscreen extent -1.75,-1.52 0.7,1.53, body extent -1.43,-1.48 1.43,1.49, height 0.92
DEC0002A [mm] "X1SON-2"
  rrect57% 0.35x0.6 smd mask+0.05: 1(-0.325,0) 2(0.325,0)
  rrect33% 0.3x0.5 on Bottom Paste: 1S(-0.35,0) 2S(0.35,0)
  body extent 0,0 0,0
ECWFD_1260x650x1270 [mm] "TH, 2-Leads, Body 12.6x6.5mm"
  round 1.4 hole 0.9: 1(-5,0) 2(5,0)
  silkscreen extent -6.32,-3.25 6.32,3.25, body extent -6.31,-3.25 6.31,3.25, height 12.71
FCC_disclaimer [mm]
FP-0215008.HXP_FUSE_CARTRIDGE-MFG [mm]
  body extent -10.35,-2.75 10.35,2.75, height 0.25
FP-970130365_SPCAER_M3-MFG [mm]
  round 3.15 hole 3.15 unplated paste-1000 mask+0: ""(0,0)
  body extent -3.46,-3 3.46,3, height 13.1
FP-860241375002_RADIAL-MFG [mm]
  rrect7% 1.4x1.4 hole 0.9 paste-1000 mask+0: 1(-2.5,0)
  round 1.4 hole 0.9 paste-1000 mask+0: 2(2.5,0)
  silkscreen extent -5.25,-5.25 5.25,5.25, body extent -5.35,-5.35 5.35,5.35, height 0.25
FP-B59770C0120A070_RADIAL-MFG [mm]
  rrect8% 1.25x1.25 hole 0.75 paste-1000 mask+0: 1(-2.5,0)
  round 1.25 hole 0.75 paste-1000 mask+0: 2(2.5,0)
  silkscreen extent -4.5,-3.75 4.5,3.75, body extent -4.6,-3.85 4.6,3.85, height 0.25
"FP-G5Q-1A4-EU DC12_PTH_RELAY_20MM0_10MM0-MFG" [mm]
  rrect5% 2x2 hole 1.3 paste-1000 mask+0: 1(-8.82,-3.81)
  round 2 hole 1.3 paste-1000 mask+0: 2(1.34,-3.81) 3(8.96,-3.81) 5(-8.82,3.81)
  silkscreen extent -10.57,-5.15 10.15,5.15, body extent -10.25,-5.25 10.25,5.25, height 0.25
FP-GBU8J_Horizontal_Face_Down_SIP4-MFG [mm]
  rrect4% 2.45x2.45 hole 1.6 paste-1000 mask+0: 1(-7.62,-14.15)
  round 2.45 hole 1.6 paste-1000 mask+0: 2(-2.54,-14.15) 3(2.54,-14.15) 4(7.62,-14.15)
  round 6 hole 6 unplated paste-1000 mask+0: ""(0,0.85)
  silkscreen extent -11.1,-16.07 11.1,9.3, body extent -11.2,-15.48 11.2,9.4, height 0.25
FP-IsoM3-275-B-L2_RADIAL-MFG [mm]
  rrect6% 1.55x1.55 hole 1 paste-1000 mask+0: 1(-3.75,0)
  round 1.55 hole 1 paste-1000 mask+0: 2(3.75,0)
  silkscreen extent -6.6,-3.45 6.6,3.45, body extent -6.7,-3.55 6.7,3.55, height 0.25
FP-SLIMDIP-S_SLIMDIP-MFG [mm]
  rrect100% 1x1.4 hole 0.75 paste-1000 mask+0: 2(-12.1,11.75) 3(-10.95,14.75) 4(-7.5,11.75) 5(-6.35,14.75) 6(-2.9,11.75) 7(-1.75,14.75) 8(1.7,11.75) 9(2.85,14.75) 10(4,11.75) 11(5.15,14.75) 12(6.3,11.75) 13(7.45,14.75) 14(8.6,11.75) 15(9.75,14.75) 16(10.9,11.75) 17(12.05,14.75) 18(13.2,11.75) 19(14.35,14.75) 20(15.5,11.75)
  rrect100% 1.5x2 hole 0.9 paste-1000 mask+0: 21(15.4,-11.75) 22(10.4,-11.75) 23(5.4,-11.75) 24(0.4,-11.75) 25(-4.6,-11.75) 26(-9.6,-11.75) 27(-14.6,-11.75)
  round 7 hole 7 unplated paste-1000 mask+0: ""(-14.9,0) ""(14.9,0)
  silkscreen extent -16.65,-9.4 16.65,11.87, body extent -18.5,-12.85 18.5,15.55, height 0.25
FP-TSW-108-07-T-D_HDR16-MFG [mm]
  rrect6% 1.57x1.57 hole 1.02 paste+0 mask+0: 1(-8.89,-1.27)
  round 1.57 hole 1.02 paste+0 mask+0: 2(-8.89,1.27) 3(-6.35,-1.27) 4(-6.35,1.27) 5(-3.81,-1.27) 6(-3.81,1.27) 7(-1.27,-1.27) 8(-1.27,1.27) 9(1.27,-1.27) 10(1.27,1.27) 11(3.81,-1.27) 12(3.81,1.27) 13(6.35,-1.27) 14(6.35,1.27) 15(8.89,-1.27) 16(8.89,1.27)
  silkscreen extent -10.35,-3.22 10.35,2.61, body extent -10.45,-2.71 10.45,2.71, height 0.25
FP-TSW-110-07-T-S_HDR10-MFG [mm]
  rrect6% 1.57x1.57 hole 1.02 paste+0 mask+0: 1(-11.43,0)
  round 1.57 hole 1.02 paste+0 mask+0: 2(-8.89,0) 3(-6.35,0) 4(-3.81,0) 5(-1.27,0) 6(1.27,0) 7(3.81,0) 8(6.35,0) 9(8.89,0) 10(11.43,0)
  silkscreen extent -12.89,-2.02 12.89,1.34, body extent -12.99,-1.44 12.99,1.44, height 0.25
IEC_HighVoltage_Small [mm]
  silkscreen extent -2.72,-2.24 2.72,2.47
IEC_HotSurface_Small [mm]
  silkscreen extent -2.72,-2.36 2.72,2.35
KY_800x500x1100 [mm] "TH, 2- Leads, Body 8x5mm, Pin Spacing 5mm"
  round 1.35 hole 0.9: 1(-2.5,0) 2(2.5,0)
  silkscreen extent -4,-2.5 4,2.5, body extent -4,-2.5 4,2.5, height 12
Label_650x200 [mil] "Thermal Transfer Label"
  round 1 on Mech14: 0(0,0)
  silkscreen extent -325,-100 325,100, body extent -325,-100 325,100, height 1
Littelfuse_0100-0020_54_56 [mm] "Littelfuse"
  round 1.8 hole 1.3: 1(-2.3,0) 2(2.3,0)
  silkscreen extent -2.25,-2.97 2.25,2.97, body extent -2.55,-2.97 2.55,2.97, height 10.6
MARK [mm]
  round 1 smd mask+0.5: 1(0,0)
  round 1 smd far side mask+0.5: 2(0,0)
  Top Layer pour cut-out: -1.5,0 -1.386,-0.574 -1.061,-1.061 -0.574,-1.386 0,-1.5 0,-1.5 0.574,-1.386 1.061,-1.061 1.386,-0.574 1.5,0 1.5,0 1.386,0.574 1.061,1.061 0.574,1.386 0,1.5 0,1.5 -0.574,1.386 -1.061,1.061 -1.386,0.574 -1.5,0
  Bottom Layer pour cut-out: -1.5,0 -1.386,-0.574 -1.061,-1.061 -0.574,-1.386 0,-1.5 0,-1.5 0.574,-1.386 1.061,-1.061 1.386,-0.574 1.5,0 1.5,0 1.386,0.574 1.061,1.061 0.574,1.386 0,1.5 0,1.5 -0.574,1.386 -1.061,1.061 -1.386,0.574 -1.5,0
Molex_70543-0038 [mm] "Header(shrouded), 2.54mm, 4x1, TH"
  rect 1.6x1.6 hole 1.09: 1(-3.81,0)
  round 1.6 hole 1.09: 2(-1.27,0) 3(1.27,0) 4(3.81,0)
  silkscreen extent -6.35,-4.06 6.35,2.54, body extent -6.35,-4.06 6.35,2.54, height 11.81
Rubycon_630x1100 [mm] "TH, 2-Leads, Dia 6.3mm, Lead Spacing 2.5mm"
  rrect50% 1.125x1.125 hole 0.75: 1(-1.25,0)
  round 1.125 hole 0.75: 2(1.25,0)
  silkscreen extent -3.4,-3.4 3.41,3.4, body extent -3.4,-3.4 3.41,3.4, height 12.51
SMA [mm] "Molded Diode, 2-Leads, Body 4.3x2.6mm, IPC Medium Density, based on OnSemi component dimensions and land pattern"
  rect 2x2 smd: 1(-2,0) 2(2,0)
  silkscreen extent -3.66,-1.57 2.79,1.57, body extent -2.6,-1.3 2.6,1.3, height 2.42
SOD-123 [mm] "On Semi recommended land pattern"
  rect 0.915x1.22 smd: 1(-1.637,0) 2(1.637,0)
  silkscreen extent -2.74,-1.17 2.03,1.17, body extent -1.93,-0.9 1.93,0.9, height 1.35
SOD-323 [mm] "NXP recommended land pattern"
  rect 0.6x0.6 smd paste-0.05: 1(-1.1,0) 2(1.1,0)
  silkscreen extent -2.06,-0.86 1.53,0.86, body extent -1.3,-0.67 1.3,0.68, height 1.1
SOT-23 [mm] "SOT23, 3-Leads, Body 2.9x1.3mm, Pitch 0.95mm, Lead Span 2.5mm, IPC Medium Density"
  rrect50% 1x0.6 smd: 1(-1.2,0.95) 2(-1.2,-0.95) 3(1.2,0)
  silkscreen extent -1.63,-1.5 0.7,1.5, body extent -1.16,-1.45 1.21,1.45, height 1
Testpoint_Keystone_Miniature [mil] "Miniature SMT test point"
  rect 135x70 smd: 1(0,0)
  silkscreen extent -78,-46 78,45, body extent -52,-20 52,20, height 61
TI_Symbol_Overlay_Small [mm]
  silkscreen extent -2.3,-2.23 2.3,2.24
Toolinghole [mm]
  round 2 hole 2 unplated: 1(0,0)
  silkscreen extent -1.41,-1.41 1.41,1.41
TP_SM_1MM [mm] "1mm Test Point, SMT"
  round 1 smd paste-0.5: 1(0,0)
WCAP-AI3H_3500x5700 [mm] "TH, 2-Leads, Dia 35mm"
  rrect50% 3x3 hole 2: 1(-5,0)
  round 3 hole 2: 2(5,0)
  body extent -17.46,-17.5 17.5,17.5, height 56.82
WCAP-FTX2_1500x1000x1600 [mm] "TH, 2-Leads, Body 15x10mm, Pin Spacing 12.5mm"
  round 1.4 hole 0.9: 1(-6.25,0) 2(6.25,0)
  silkscreen extent -7.52,-5 7.48,5, body extent -7.5,-5 7.5,5, height 16
WCAP-FTX2_1800x600x1200 [mm] "TH, 2-Leads, Body 18x6mm, Lead Spacing 15mm"
  round 1.6 hole 1.1: 1(-7.5,0) 2(7.5,0)
  silkscreen extent -9.25,-3.25 9.25,3.25, body extent -9.25,-3.25 9.25,3.25, height 12.5
WE-CMBNC_L [mm] "TH, 4-Leads, Body 19x28mm"
  rrect6% 1.7x1.7 hole 1.2: 1(-6,5)
  round 1.7 hole 1.2: 2(-6,-5) 3(6,-5) 4(6,5)
  silkscreen extent -9,-13.75 9,13.75, body extent -9,-13.75 9,13.75, height 25.47
WE-MAIA_3015 [mm] "SMD, 2-Leads, Body 3x3mm"
  rect 1.3x3.4 smd: 1(-1.05,0) 2(1.05,0)
  silkscreen extent -0.1,-1.6 0.1,1.6, body extent -1.6,-1.6 1.6,1.6, height 1.5
WE-TI_8095 [mm] "Wurth WE-TI 8095"
  rect 1.6x1.6 hole 1: 1(-2.5,0)
  round 1.6 hole 1: 2(2.5,0)
  silkscreen extent -4.79,-4.15 4.15,4.15, body extent -4.12,-4.14 4.15,4.14, height 10
WEEE_Minimum [mm] "WEEElie bin"
  silkscreen extent -2.42,-4.38 2.52,2.65
"White oil-26X4" [mm] "¶þÎ¬Âë°×ÓÍ¿ò"
  silkscreen extent -26,0 0,4

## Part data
C19 C31 C54 C78: library part CMP-0007402-3, "CAP, CERM, 1000 pF, 25 V, +/- 10%, X7R, 0603", Cap_Case=0603, Manufacturer=MuRata, Supplier Part Number 1=GRM188R71E102KA01D-ND, TempCo=X7R, Tolerance_%=10%, Value1=Unknown, Value2=25V, ValueDisplayed=1000pF
C32 C57 C60 C62 C72: library part CMP-0008310-1, "CAP, CERM, 10 uF, 35 V, +/- 10%, X5R, 0805", Cap_Case=0805, Manufacturer=MuRata, Supplier Part Number 1=490-10514-1-ND, TempCo=X5R, Tolerance_%=10%, Value1=Unknown, Value2=35V, ValueDisplayed=10uF
C33 C40: library part CMP-0067532-1, "CAP, CERM, 2200 pF, X1 250 VAC/Y2 250 VAC, +/- 20%, E, 8x5mm", Cap_Case=8x5x11mm, Manufacturer=MuRata, Supplier Part Number 1=490-9468-ND, TempCo=E, Tolerance_%=20%, Value1=Unknown, Value2=V, ValueDisplayed=2200pF
C34: library part CMP-0012313-1, "CAP, Film, 0.47 uF, 275 V, +/- 10%, TH", Cap_Case=15x10x16mm, Manufacturer="Wurth Elektronik", Supplier Part Number 1=732-5890-ND, Tolerance_%=10%, Value1=Unknown, Value2=275V, ValueDisplayed=0.47uF
C35: library part CMP-0007193-4, "CAP, CERM, 20 pF, 50 V, +/- 5%, C0G/NP0, 0603", Cap_Case=0603, Manufacturer=MuRata, Supplier Part Number 1=490-1410-1-ND, TempCo=C0G/NP0, Tolerance_%=5%, Value1=Unknown, Value2=50V, ValueDisplayed=20pF
C36 C43 C45 C53 C58 C61 C63 C74 C75 C76 C84: library part CMP-0007144-4, "CAP, CERM, 0.1 uF, 50 V, +/- 10%, X7R, 0603", Cap_Case=0603, Manufacturer=MuRata, Supplier Part Number 1=490-4779-1-ND, TempCo=X7R, Tolerance_%=10%, Value1="0.02 ohm", Value2=50V, ValueDisplayed=0.1uF
C37: library part CMP-0008227-2, "CAP, CERM, 0.33 uF, 50 V, +/- 10%, X7R, 0805", Cap_Case=0805, Manufacturer=MuRata, Supplier Part Number 1=490-3327-1-ND, TempCo=X7R, Tolerance_%=10%, Value1=Unknown, Value2=50V, ValueDisplayed=0.33uF
C38: library part CMP-0084882-1, "CAP, AL, 680 µF, 450 V, +/- 20%, TH", Cap_Case=35x57mm, Manufacturer="Wurth Elektronik", Tolerance_%=20%, Value2=450V, ValueDisplayed=680µF
C39: library part CMP-0012314-3, "CAP, Film, 0.1 uF, 275 V, +/- 10%, TH", Cap_Case=18x6x12mm, Manufacturer="Wurth Elektronik", Supplier Part Number 1=732-5898-ND, Tolerance_%=10%, Value1=Unknown, Value2=275V, ValueDisplayed=0.1uF
C41: library part CMP-0080807-1, "CAP, AL, 100 µF, 35 V, +/- 20%, TH", Cap_Case=6.3x11, Manufacturer=Rubycon, Supplier Part Number 1=1189-2268-ND, Tolerance_%=20%, Value2=35V, ValueDisplayed=100µF
C42: library part CMP-0096475-1, "10 µF 400 V Aluminum Electrolytic Capacitors Radial, Can 10000 Hrs @ 105°C", Digikey Part Number=732-9301-1-ND, Leakage Current=260uA, Manufacturer="Wurth Electronics", Mouser Part Number=710-860241375002, Operating Temperature Range="-25°C to +105°C", Tolerance_%=20%, ValueDisplayed=10uF
C44: library part CMP-0081637-1, "CAP, CERM, 10 µF, 35 V,+/- 10%, X5R, 1206", Cap_Case=1206, Manufacturer=MuRata, Supplier Part Number 1=490-9964-1-ND, TempCo=X5R, Tolerance_%=10%, Value1="0.001 ohm", Value2=35V, ValueDisplayed=10µF
C46 C47 C49 C50 C51 C52: library part CMP-0008965-2, "CAP, CERM, 10 uF, 25 V, +/- 10%, X7R, 1206", Cap_Case=2220, Manufacturer=MuRata, Supplier Part Number 1=81-GRM31CR71E106KA12, TempCo=X7R, Tolerance_%=10%, Value1=Unknown, Value2=25V, ValueDisplayed=10uF
C48 C79: library part CMP-0007171-4, "CAP, CERM, 100 pF, 50 V, +/- 5%, C0G/NP0, 0603", Cap_Case=0603, Manufacturer=MuRata, Supplier Part Number 1=490-1427-1-ND, TempCo=C0G/NP0, Tolerance_%=5%, Value1=Unknown, Value2=50V, ValueDisplayed=100pF
C56 C70 C71 C73: library part CMP-0007457-2, "CAP, CERM, 0.047 uF, 50 V, +/- 10%, X7R, 0603", Cap_Case=0603, Manufacturer=MuRata, Supplier Part Number 1=490-3287-1-ND, TempCo=X7R, Tolerance_%=10%, Value1=Unknown, Value2=50V, ValueDisplayed=0.047uF
C59: library part CMP-0012508-3, "CAP, Film, 0.47 uF, 450 V, +/- 10%, TH", Cap_Case=12.6x6.5x12.7mm, Manufacturer=Panasonic, Supplier Part Number 1=P16727-ND, Tolerance_%=10%, Value1=Unknown, Value2=450V, ValueDisplayed=0.47uF
C64 C65 C66 C67 C68 C69: library part CMP-0007442-5, "CAP, CERM, 220 pF, 50 V, +/- 10%, X7R, 0603", Cap_Case=0603, Manufacturer=MuRata, Supplier Part Number 1=490-1483-1-ND, TempCo=X7R, Tolerance_%=10%, Value1=Unknown, Value2=50V, ValueDisplayed=220pF
C77 C83: library part CMP-0007402-1, "CAP, CERM, 1000 pF, 25 V, +/- 10%, X7R, 0603", Cap_Case=0603, Manufacturer=MuRata, Supplier Part Number 1=GRM188R71E102KA01D-ND, TempCo=X7R, Tolerance_%=10%, Value1=Unknown, Value2=25V, ValueDisplayed=1000pF
C81 C82: library part CMP-0079720-2, "CAP, CERM, 1 µF, 25 V,+/- 10%, X7R, 0603", Cap_Case=0603, Manufacturer=MuRata, Supplier Part Number 1=490-10888-1-ND, TempCo=X7R, Tolerance_%=10%, Value2=25V, ValueDisplayed=1µF
D3 D12: library part CMP-0028457-2, "Diode, Schottky, 30 V, 0.2 A, SOD-123", Manufacturer="ON Semiconductor", Value1=0.2A, Value2=0.8V
D4 D7: library part CMP-0076882-1, "Diode, Ultrafast, 1000 V, 1 A, SMA", Manufacturer="Diodes Inc.", Supplier Part Number 1=US1M-FDICT-ND, Value1=1A, Value2=1.7V
D5: library part CMP-0096899-4, "Bridge Rectifier Single Phase Standard 600 V Through Hole GBU", Digikey Part Number=2721-GBU8J-ND, Forward Current=5.6A, Manufacturer=Diotec, Max Surge Forward Current=180A, Mouser Part Number=637-GBU8J, Operating Temperature Range="-50°C to +150°C", Part Number=GBU8J, Peak Reverse Current=5uA, ValueDisplayed=80pF
D6 D8 D9 D10 D11: library part CMP-0005835-4, "Diode, Zener, 18 V, 200 mW, SOD-323", Manufacturer="Diodes Inc.", Power_W=200mW, Value1=0.2W
F1: library part CMP-0097018-1, "Fuse Miniature Slow Blow Acting 8A 250V Holder Cartridge 5 X 20mm Ceramic Bulk", Digikey Part Number=F2668-ND, Fuse Current=8A, Fuse Voltage Drop=100mV, Manufacturer="Littelfuse Inc", Mouser Part Number=576-0215008.HXP, Operating Temperature Range="-55°C to +125°C"
J5 J10: library part CMP-1502-03325-2
J14: library part CMP-0055267-1, "Header(shrouded), 2.54mm, 4x1, Tin, TH", Color=Black, Manufacturer=Molex, Supplier Part Number 1=WM4826-ND
J15: library part CMP-0123024-2, "Connector Header Through Hole 16 position 0.100\" (2.54mm)", Digikey Part Number=SAM1034-08-ND, Manufacturer=Samtec, Mouser Part Number=200-TSW10807TD, Octopart Part Number=2b95e29b26b6f452, Operating Temperature Range="-55°C to +105°C"
J16 J17 J18: library part CMP-0123044-2, "Conn Unshrouded Header HDR 10 POS 2.54mm Solder ST Top Entry Thru-Hole Bag", Digikey Part Number=SAM1035-10-ND, Manufacturer=Samtec, Mouser Part Number=200-TSW11007TS, Octopart Part Number=7b82b28c769da445, Operating Temperature Range="-55°C to +105°C"
K1: library part CMP-0096783-1, "Electromechanical Relay SPST-NO 5(NO)/3(NC)ADC/10(NO)/3(NC)AAC 12VDC 720Ohm Through Hole", Coil Current_A=16.7mA, Coil Power_W=200mW, Coil Resistance=720¦¸, Coil Voltage_VDC=12V, Contact Rating_A=10A, Digikey Part Number=Z5836-ND, Manufacturer=Omron, Mouser Part Number=653-G5Q-1A4-EUDC12, Operating Temperature Range="-40°C to +85°C", Switching Current=3/5A
L2: library part CMP-0013082-2, "Coupled inductor, 7 mH, 7 A, 0.02 ohm, TH", Manufacturer="Wurth Elektronik", Supplier Part Number 1=732-5589-ND, ValueDisplayed=7mH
